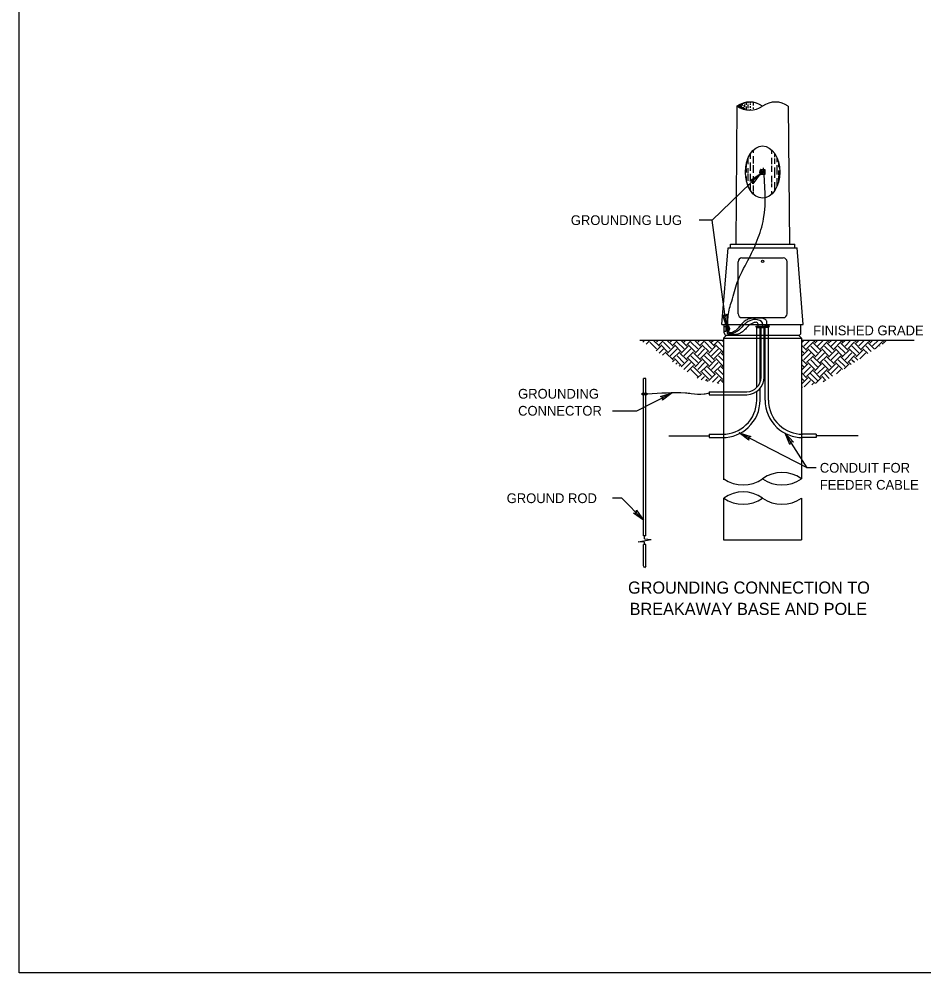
# Model space of a CAD drawing. Extents: x 99978 to 113378, y 99891 to 102182.
# Drawn here: x 99978 to 101096, y 99891 to 101068 of the extents above; entities that cross this region are included whole.
import ezdxf

# ---------------------------------------------------------------- set-up
doc = ezdxf.new("R2010")
doc.units = 0
doc.layers.add('Border Organizer Shape', color=7, linetype='Continuous')
doc.layers.add('Default', color=7, linetype='Continuous')

msp = doc.modelspace()

# ---------------------------------------------------------------- linework, layer by layer
at = {"layer": 'Border Organizer Shape'}
for p, q in [((100865.1, 100960.7), (100863.6, 100790.4)), ((100865.2, 100960.6), (100865.2, 100960.7)), ((100865.5, 100960.4), (100865.5, 100960.9)), ((100865.8, 100960.8), (100865.8, 100961.1)), ((100865.8, 100960.2), (100865.8, 100960.5)), ((100866.2, 100961.1), (100866.2, 100961.4)), ((100866.2, 100960), (100866.2, 100960.9)), ((100866.7, 100961), (100866.7, 100961.7)), ((100866.7, 100959.7), (100866.7, 100960.1)), ((100867.1, 100961), (100867.1, 100961.9)), ((100867.1, 100959.4), (100867.1, 100960.7)), ((100867.7, 100960.5), (100867.7, 100962.3)), ((100867.7, 100959.1), (100867.7, 100959.7)), ((100868.4, 100961.4), (100868.4, 100962.6)), ((100868.4, 100958.7), (100868.4, 100960.4)), ((100869, 100962.3), (100869, 100962.9)), ((100869, 100960.3), (100869, 100961)), ((100869, 100958.4), (100869, 100959.9)), ((100869.7, 100961.9), (100869.7, 100963.2)), ((100869.7, 100961.1), (100869.7, 100961.5)), ((100869.7, 100958.1), (100869.7, 100959.8)), ((100870.7, 100961.7), (100870.7, 100963.7)), ((100870.7, 100958.6), (100870.7, 100960.9)), ((100870.7, 100957.7), (100870.7, 100958.5)), ((100872, 100961.6), (100872, 100964.1)), ((100872, 100957.2), (100872, 100959.6)), ((100873.4, 100963.5), (100873.4, 100964.6)), ((100873.4, 100960.5), (100873.4, 100961.6)), ((100873.4, 100956.8), (100873.4, 100959.6)), ((100875, 100963.8), (100875, 100965)), ((100875, 100959.6), (100875, 100962.9)), ((100875, 100956.3), (100875, 100958.1)), ((100876.9, 100964.3), (100876.9, 100965.3)), ((100876.9, 100962.2), (100876.9, 100964)), ((100876.9, 100957.9), (100876.9, 100960.3)), ((100876.9, 100956), (100876.9, 100957.3)), ((100878.8, 100964.3), (100878.8, 100965.5)), ((100878.8, 100961), (100878.8, 100962.8)), ((100878.8, 100958), (100878.8, 100960.5)), ((100878.8, 100955.8), (100878.8, 100956.7)), ((100881.7, 100964.3), (100881.7, 100965.6)), ((100881.7, 100962.3), (100881.7, 100963.7)), ((100881.7, 100958.7), (100881.7, 100960.5)), ((100881.7, 100955.7), (100881.7, 100956.9)), ((100885.4, 100964.2), (100885.4, 100965.3)), ((100885.4, 100961.5), (100885.4, 100963.8)), ((100885.4, 100957.3), (100885.4, 100959.2)), ((100928.4, 100960.7), (100929.9, 100790.4)), ((100878.8, 100889.1), (100878.8, 100896.7)), ((100881.7, 100895.5), (100881.7, 100902)), ((100885.4, 100903.1), (100885.4, 100906.6)), ((100885.4, 100889.7), (100885.4, 100899.1)), ((100908.1, 100901.8), (100908.1, 100906.6)), ((100908.1, 100889.1), (100908.1, 100897)), ((100911.9, 100897.6), (100911.9, 100902)), ((100876.9, 100885), (100876.9, 100891.1)), ((100881.7, 100880.9), (100881.7, 100891.1)), ((100885.4, 100878.2), (100885.4, 100888)), ((100908.1, 100879.6), (100908.1, 100887.1)), ((100911.9, 100889.5), (100911.9, 100896.1)), ((100911.9, 100872.3), (100911.9, 100884.8)), ((100914.8, 100891.5), (100914.8, 100896.6)), ((100914.8, 100876.2), (100914.8, 100887.8)), ((100916.7, 100885.3), (100916.7, 100890.9)), ((100893.7, 100877), (100834.3, 100819.9)), ((100876.9, 100878.7), (100876.9, 100883.8)), ((100876.9, 100867.5), (100876.9, 100874)), ((100878.8, 100877.7), (100878.8, 100884.2)), ((100878.8, 100868.3), (100878.8, 100876.5)), ((100881.7, 100867.6), (100881.7, 100877.2)), ((100885.4, 100866.5), (100885.4, 100874.3)), ((100896.7, 100880), (100894.1, 100880)), ((100896.7, 100878.6), (100894.1, 100878.6)), ((100908.1, 100866.4), (100908.1, 100874.5)), ((100916.7, 100875), (100916.7, 100881.1)), ((100916.7, 100867.8), (100916.7, 100874.1)), ((100878.8, 100861.9), (100878.8, 100864.4)), ((100881.7, 100856.5), (100881.7, 100864.2)), ((100885.4, 100855.9), (100885.4, 100862.9)), ((100908.1, 100860.8), (100908.1, 100865.1)), ((100911.9, 100856.5), (100911.9, 100867)), ((100914.8, 100862.1), (100914.8, 100871.9)), ((100885.4, 100852), (100885.4, 100854.8)), ((100908.1, 100852.1), (100908.1, 100855.8)), ((100852.3, 100688.7), (100834.3, 100819.9)), ((100846.6, 100691.1), (100854.2, 100785.7)), ((100854.2, 100785.7), (100939.3, 100785.7)), ((100857.1, 100790.4), (100936.4, 100790.4)), ((100857.1, 100785.7), (100857.1, 100790.4)), ((100936.4, 100785.7), (100936.4, 100790.4)), ((100946.9, 100691.1), (100939.3, 100785.7)), ((100866.5, 100704.3), (100866.5, 100768.6)), ((100871.2, 100773.4), (100922.3, 100773.4)), ((100927, 100704.3), (100927, 100768.6)), ((100871.2, 100699.6), (100922.3, 100699.6)), ((100846.6, 100691.1), (100946.9, 100691.1)), ((100849.5, 100680.7), (100849.5, 100691.1)), ((100849.5, 100688.7), (100851.2, 100688.7)), ((100851.2, 100688.7), (100851.2, 100683)), ((100852.2, 100686.8), (100851.2, 100686.8)), ((100852.2, 100684.9), (100851.2, 100684.9)), ((100852.7, 100686.6), (100852.2, 100686.6)), ((100852.7, 100685.1), (100852.2, 100685.1)), ((100855.7, 100686.6), (100855.3, 100686.6)), ((100855.7, 100685.1), (100855.3, 100685.1)), ((100888.3, 100689.1), (100894.3, 100689.1)), ((100889.5, 100687.3), (100888.3, 100689.1)), ((100889.5, 100687.3), (100893.7, 100687.3)), ((100889.5, 100677.8), (100889.5, 100687.3)), ((100893.7, 100689.1), (100899.8, 100689.1)), ((100894.9, 100687.3), (100893.7, 100689.1)), ((100893.7, 100687.3), (100894.3, 100687.9)), ((100893.7, 100677.8), (100893.7, 100687.3)), ((100894.9, 100687.3), (100898.6, 100687.3)), ((100894.9, 100677.8), (100894.9, 100687.3)), ((100898.6, 100687.3), (100899.8, 100689.1)), ((100898.6, 100677.8), (100898.6, 100687.3)), ((100905.2, 100689.1), (100899.2, 100689.1)), ((100899.8, 100687.3), (100899.2, 100687.9)), ((100904, 100687.3), (100899.8, 100687.3)), ((100899.8, 100677.8), (100899.8, 100687.3)), ((100904, 100687.3), (100905.2, 100689.1)), ((100904, 100677.8), (100904, 100687.3)), ((100944.1, 100680.7), (100944.1, 100691.1)), ((100852.3, 100677.8), (100848.6, 100674.2)), ((100848.6, 100674.2), (100944.9, 100674.2)), ((100848.6, 100674.2), (100848.6, 100499.2)), ((100849.5, 100683), (100851.2, 100683)), ((100852.3, 100677.8), (100941.2, 100677.8)), ((100852.3, 100677.8), (100941.2, 100677.8)), ((100889.5, 100613.5), (100889.5, 100677.8)), ((100893.7, 100619.7), (100893.7, 100677.8)), ((100894.9, 100626.4), (100894.9, 100677.8)), ((100898.6, 100626.1), (100898.6, 100677.8)), ((100899.8, 100597.8), (100899.8, 100677.8)), ((100904, 100597.8), (100904, 100677.8)), ((100941.2, 100677.8), (100944.9, 100674.2)), ((100944.9, 100674.2), (100944.9, 100500.7)), ((100745.2, 100671.8), (100848.6, 100671.8)), ((100748.9, 100669.4), (100751.3, 100671.8)), ((100753, 100666.7), (100758.1, 100671.8)), ((100757.4, 100669.4), (100765.9, 100660.9)), ((100761.8, 100671.8), (100769.3, 100664.3)), ((100765.2, 100658.6), (100770.9, 100664.3)), ((100765.8, 100669.4), (100768.2, 100671.8)), ((100769.2, 100666), (100775, 100671.8)), ((100770.9, 100666), (100779.4, 100657.5)), ((100774.3, 100669.4), (100782.8, 100660.9)), ((100778.6, 100671.8), (100786.2, 100664.3)), ((100779.3, 100655.8), (100787.8, 100664.3)), ((100782.8, 100669.4), (100785.2, 100671.8)), ((100786.2, 100666), (100792, 100671.8)), ((100787.9, 100666), (100796.4, 100657.5)), ((100791.3, 100669.4), (100799.8, 100660.9)), ((100795.8, 100671.8), (100803.3, 100664.3)), ((100796.3, 100655.8), (100804.8, 100664.3)), ((100799.7, 100669.4), (100802.1, 100671.8)), ((100803.1, 100666), (100808.9, 100671.8)), ((100804.8, 100666), (100813.3, 100657.5)), ((100808.2, 100669.4), (100816.7, 100660.9)), ((100812.7, 100671.8), (100820.1, 100664.3)), ((100813.3, 100655.9), (100821.8, 100664.4)), ((100816.7, 100669.4), (100819.1, 100671.8)), ((100820.1, 100666), (100825.9, 100671.8)), ((100821.9, 100666.1), (100830.4, 100657.6)), ((100825.3, 100669.5), (100833.8, 100661)), ((100829.8, 100671.8), (100837.2, 100664.4)), ((100830.3, 100655.9), (100838.8, 100664.4)), ((100833.7, 100669.5), (100836, 100671.8)), ((100837.1, 100666.1), (100842.8, 100671.8)), ((100838.8, 100666.1), (100847.3, 100657.6)), ((100842.2, 100669.5), (100848.6, 100663)), ((100846.7, 100671.8), (100848.6, 100669.8)), ((100944.9, 100671.8), (101083.8, 100671.8)), ((100944.9, 100668.5), (100948.2, 100671.8)), ((100944.9, 100665.7), (100951.2, 100659.4)), ((100947.7, 100664.5), (100955, 100671.8)), ((100951.1, 100661.1), (100959.6, 100669.6)), ((100956.2, 100664.5), (100964.7, 100656)), ((100959.2, 100671.8), (100961.4, 100669.6)), ((100959.6, 100667.9), (100968.1, 100659.4)), ((100961.3, 100667.9), (100965.2, 100671.8)), ((100964.7, 100664.5), (100972, 100671.8)), ((100968.1, 100661.1), (100976.6, 100669.6)), ((100969.8, 100661.1), (100978.3, 100652.6)), ((100973.2, 100664.5), (100981.7, 100656)), ((100976, 100671.8), (100978.3, 100669.6)), ((100976.6, 100667.9), (100985.1, 100659.4)), ((100978.2, 100667.9), (100982.1, 100671.8)), ((100981.6, 100664.5), (100988.9, 100671.8)), ((100985, 100661.1), (100993.5, 100669.6)), ((100986.7, 100661.1), (100995.2, 100652.6)), ((100990.1, 100664.5), (100998.6, 100656)), ((100993.2, 100671.8), (100995.4, 100669.6)), ((100993.5, 100667.9), (101002, 100659.4)), ((100995.2, 100667.9), (100999.1, 100671.8)), ((100998.6, 100664.5), (101005.9, 100671.8)), ((101002, 100661.1), (101010.5, 100669.6)), ((101003.8, 100661.2), (101012.3, 100652.7)), ((101007.2, 100664.6), (101015.7, 100656.1)), ((101010.1, 100671.8), (101012.2, 100669.6)), ((101010.6, 100668), (101019.1, 100659.5)), ((101012.2, 100668), (101016, 100671.8)), ((101015.6, 100664.6), (101022.8, 100671.8)), ((101019, 100661.2), (101027.5, 100669.7)), ((101020.7, 100661.2), (101026.7, 100655.1)), ((101024.1, 100664.6), (101030.9, 100657.8)), ((101027.2, 100671.8), (101029.3, 100669.7)), ((101027.5, 100668), (101035, 100660.5)), ((101029.2, 100668), (101033, 100671.8)), ((101032.6, 100664.6), (101039.8, 100671.8)), ((101036, 100661.2), (101044.5, 100669.7)), ((101041.2, 100664.6), (101041.3, 100664.5)), ((101044.1, 100671.8), (101046.2, 100669.7)), ((101044.6, 100668), (101045.5, 100667.2)), ((101046.1, 100668), (101049.9, 100671.8)), ((100769.2, 100655.8), (100774.3, 100660.9)), ((100773.3, 100653.1), (100777.7, 100657.5)), ((100777.7, 100655.8), (100786.2, 100647.3)), ((100782.7, 100652.4), (100791.2, 100660.9)), ((100786.1, 100649), (100794.6, 100657.5)), ((100791.2, 100652.4), (100799.7, 100643.9)), ((100794.6, 100655.8), (100803.1, 100647.3)), ((100799.7, 100652.4), (100808.2, 100660.9)), ((100803.1, 100649), (100811.6, 100657.5)), ((100808.3, 100652.5), (100816.8, 100644)), ((100811.7, 100655.9), (100820.2, 100647.4)), ((100816.7, 100652.5), (100825.2, 100661)), ((100820.1, 100649.1), (100828.6, 100657.6)), ((100825.2, 100652.5), (100833.7, 100644)), ((100828.6, 100655.9), (100837.1, 100647.4)), ((100833.7, 100652.5), (100842.2, 100661)), ((100837.1, 100649.1), (100845.6, 100657.6)), ((100842.3, 100652.5), (100848.6, 100646.2)), ((100845.7, 100655.9), (100848.6, 100653)), ((100847.2, 100655.9), (100848.6, 100657.3)), ((100944.9, 100651.5), (100952.8, 100659.4)), ((100944.9, 100658.9), (100947.8, 100656)), ((100947.7, 100647.4), (100956.2, 100656)), ((100951.1, 100644), (100959.6, 100652.5)), ((100952.8, 100661.1), (100961.3, 100652.5)), ((100959.6, 100650.9), (100968.1, 100642.4)), ((100961.2, 100650.9), (100969.7, 100659.4)), ((100964.6, 100647.5), (100973.1, 100656)), ((100968, 100644.1), (100976.5, 100652.6)), ((100976.5, 100650.9), (100985, 100642.4)), ((100978.2, 100650.9), (100986.7, 100659.4)), ((100981.6, 100647.5), (100990.1, 100656)), ((100985, 100644.1), (100993.5, 100652.6)), ((100993.6, 100651), (101002.1, 100642.5)), ((100995.2, 100651), (101003.7, 100659.5)), ((100998.6, 100647.6), (101007.1, 100656.1)), ((101002, 100644.2), (101010.5, 100652.7)), ((101010.5, 100651), (101014.3, 100647.1)), ((101012.2, 100651), (101020.7, 100659.5)), ((101016.7, 100648.7), (101024.1, 100656.1)), ((100785.5, 100645), (100787.8, 100647.3)), ((100787.8, 100649), (100796.3, 100640.5)), ((100789.6, 100642.3), (100791.2, 100643.9)), ((100793.7, 100639.6), (100794.6, 100640.5)), ((100796.3, 100638.9), (100804.8, 100647.4)), ((100799.7, 100635.5), (100808.2, 100644)), ((100803.8, 100632.8), (100811.6, 100640.6)), ((100804.9, 100649.1), (100813.4, 100640.6)), ((100811.6, 100638.9), (100820.1, 100630.4)), ((100813.3, 100638.9), (100821.8, 100647.4)), ((100816.7, 100635.5), (100825.2, 100644)), ((100820.1, 100632.1), (100828.6, 100640.6)), ((100821.8, 100649.1), (100830.3, 100640.6)), ((100828.6, 100638.9), (100837.2, 100630.4)), ((100830.2, 100638.9), (100838.7, 100647.4)), ((100833.6, 100635.5), (100842.1, 100644)), ((100837, 100632.1), (100845.5, 100640.6)), ((100838.9, 100649.1), (100847.4, 100640.6)), ((100845.5, 100638.9), (100848.6, 100635.8)), ((100847.2, 100638.9), (100848.6, 100640.3)), ((100944.9, 100648.5), (100951.1, 100642.3)), ((100944.9, 100634.6), (100952.7, 100642.4)), ((100944.9, 100641.7), (100947.7, 100638.9)), ((100947.6, 100630.5), (100956.1, 100639)), ((100952.8, 100644.1), (100961.3, 100635.6)), ((100956.2, 100647.5), (100964.7, 100639)), ((100961.2, 100633.9), (100969.7, 100642.4)), ((100964.6, 100630.5), (100973.1, 100639)), ((100969.7, 100644.1), (100978.2, 100635.6)), ((100973.1, 100647.5), (100981.6, 100639)), ((100978.2, 100634), (100986.7, 100642.5)), ((100981.6, 100630.6), (100990.1, 100639.1)), ((100986.8, 100644.2), (100995.3, 100635.7)), ((100990.2, 100647.6), (100998.7, 100639.1)), ((100997.7, 100636.5), (101003.7, 100642.5)), ((101003.7, 100644.2), (101006, 100641.8)), ((101007.1, 100647.6), (101010.2, 100644.5)), ((100808.2, 100635.5), (100816.7, 100627)), ((100816, 100624.7), (100821.7, 100630.4)), ((100821, 100622.9), (100825.1, 100627)), ((100821.8, 100632.1), (100830.3, 100623.6)), ((100825.2, 100635.5), (100833.7, 100627)), ((100830.2, 100621.9), (100838.7, 100630.4)), ((100835, 100619.8), (100842.1, 100627)), ((100838.7, 100632.1), (100847.2, 100623.6)), ((100842.1, 100635.5), (100848.6, 100629)), ((100944.9, 100631.7), (100951.1, 100625.4)), ((100951, 100627.1), (100959.5, 100635.6)), ((100952.7, 100627.1), (100961.2, 100618.6)), ((100956.1, 100630.5), (100964.6, 100622)), ((100959.5, 100633.9), (100968, 100625.4)), ((100968, 100627.1), (100976.5, 100635.6)), ((100969.8, 100627.2), (100975, 100621.9)), ((100973.2, 100630.6), (100979.2, 100624.6)), ((100976.6, 100634), (100983.3, 100627.2)), ((100988.2, 100630.4), (100993.5, 100635.7)), ((100993.5, 100634), (100993.6, 100633.8)), ((100749.8, 100606.2), (100749.8, 100624.4)), ((100752.4, 100624.4), (100749.8, 100624.4)), ((100752.4, 100606.2), (100752.4, 100624.4)), ((100826.6, 100621.7), (100828.5, 100623.6)), ((100828.5, 100621.9), (100829.4, 100621)), ((100840.5, 100618.6), (100845.5, 100623.6)), ((100842.2, 100618.6), (100842.6, 100618.2)), ((100845.6, 100622), (100848.6, 100618.9)), ((100847.2, 100622), (100848.6, 100623.4)), ((100944.9, 100617.5), (100952.7, 100625.4)), ((100944.9, 100624.9), (100947.7, 100622)), ((100944.9, 100614.5), (100946, 100613.4)), ((100948.1, 100614), (100956.1, 100622)), ((100957.7, 100616.8), (100959.5, 100618.6)), ((100962.3, 100618.1), (100969.7, 100625.5)), ((100971.8, 100620.8), (100973.1, 100622)), ((100741.5, 100584.7), (100785.2, 100606.6)), ((100749.8, 100430.3), (100749.8, 100604.4)), ((100752.4, 100430.3), (100752.4, 100604.4)), ((100830.6, 100608.1), (100830.6, 100604.4)), ((100830.6, 100608.1), (100848.6, 100608.1)), ((100830.6, 100604.4), (100848.6, 100604.4)), ((100848.6, 100608.1), (100877.5, 100608.1)), ((100848.6, 100604.4), (100877.5, 100604.4)), ((100889.5, 100597.8), (100889.5, 100607.8)), ((100893.7, 100597.8), (100893.7, 100612)), ((100711.5, 100584.6), (100741.5, 100584.7)), ((100830.6, 100555.7), (100847.4, 100555.7)), ((100830.6, 100555.7), (100830.6, 100551.5)), ((100951.7, 100514.2), (100867.9, 100557.5)), ((100951.7, 100514.2), (100924.7, 100557)), ((100962.9, 100555.7), (100946.1, 100555.7)), ((100962.9, 100555.7), (100962.9, 100551.5)), ((100780.8, 100553.6), (100830.6, 100553.6)), ((100830.6, 100551.5), (100847.4, 100551.5)), ((100962.9, 100551.5), (100946.1, 100551.5)), ((101014.7, 100553.6), (100962.9, 100553.6)), ((100963, 100514.2), (100951.7, 100514.2)), ((100722.9, 100476.6), (100711.6, 100476.6)), ((100749.8, 100449.5), (100722.9, 100476.6)), ((100848.6, 100476.8), (100848.6, 100425.2)), ((100944.9, 100476.8), (100944.9, 100425.2)), ((100742.9, 100422.8), (100759.2, 100425.7)), ((100752.4, 100430.3), (100749.8, 100430.3)), ((100751.1, 100426.4), (100751.1, 100430.3)), ((100751.1, 100426.4), (100759.2, 100425.7)), ((100751.1, 100422.2), (100742.9, 100422.8)), ((100749.8, 100393.2), (100749.8, 100419.5)), ((100752.4, 100419.5), (100749.8, 100419.5)), ((100751.1, 100419.5), (100751.1, 100422.2)), ((100752.4, 100393.2), (100752.4, 100419.5)), ((100848.6, 100425.2), (100944.9, 100425.2)), ((100751.1, 100390.8), (100749.8, 100393.2)), ((100752.4, 100393.2), (100751.1, 100390.8))]:
    msp.add_line(p, q, dxfattribs=at)
for points in [[(100881.2, 100868.5), (100893.7, 100877), (100884.7, 100864.9), (100884.7, 100868.3)], [(100852.8, 100703.8), (100852.3, 100688.7), (100847.8, 100703.1), (100850.6, 100701.1)], [(100754, 100604.4), (100748.1, 100604.4), (100748.1, 100606.2), (100754, 100606.2)], [(100770.7, 100602.2), (100785.2, 100606.6), (100773, 100597.7), (100773.9, 100601)], [(100879.9, 100548.4), (100867.9, 100557.5), (100882.3, 100552.9), (100879, 100551.7)], [(100930.5, 100543), (100924.7, 100557), (100934.8, 100545.7), (100931.4, 100546.4)], [(100741.1, 100461.9), (100749.8, 100449.5), (100737.5, 100458.3), (100740.9, 100458.4)]]:
    msp.add_lwpolyline(points, close=True, dxfattribs=at)
for points in [[(100894.1, 100877.2), (100894.1, 100876.5), (100899.8, 100876.5), (100899.8, 100882.2), (100894.1, 100882.2), (100894.1, 100881.5)], [(100834.3, 100819.9), (100818.5, 100819.9)], [(100853.6, 100688.7), (100852.2, 100688.7), (100852.2, 100683), (100853.6, 100683)], [(100855.7, 100686.6), (100855.7, 100688.7), (100854.3, 100688.7)], [(100854.3, 100683), (100855.7, 100683), (100855.7, 100685.1)]]:
    msp.add_lwpolyline(points, dxfattribs=at)
msp.add_circle((100896.8, 100769), 1.42, dxfattribs=at)
for centre, radius, start, end in [((100880.9, 100938), 27.7, 55.146, 124.854), ((100880.9, 100983.4), 27.7, 235.146, 304.854), ((100912.6, 100938), 27.7, 55.146, 124.854), ((100897.7, 100879.3), 4.54, 141.3402, 218.6598), ((100894.1, 100879.3), 0.709, 90, 270), ((100894.5, 100881.9), 0.454, 38.6598, 141.3402), ((100894.1, 100877.2), 4.26, 40.5831, 89.9989), ((100894.1, 100881.5), 4.26, 269.9969, 319.4163), ((100894.5, 100876.8), 0.454, 218.6598, 321.3402), ((100891.3, 100879.3), 4.54, 8.9819, 25.2023), ((100891.3, 100879.3), 4.54, 334.7901, 351.0122), ((100896.7, 100879.3), 0.709, 270, 90), ((100896.7, 100879.3), 0.895, 314.2773, 45.723), ((100871.2, 100768.6), 4.73, 90, 180), ((100922.3, 100768.6), 4.73, 0, 90), ((100871.2, 100704.3), 4.73, 180, 270), ((100922.3, 100704.3), 4.73, 270, 0), ((100857.2, 100685.9), 4.54, 141.3402, 218.6598), ((100854, 100688.4), 0.454, 38.6598, 141.3402), ((100850.8, 100685.9), 4.54, 321.3402, 38.6598), ((100855.7, 100685.9), 0.709, 270, 90), ((100852.3, 100680.7), 2.84, 180, 270), ((100854, 100683.3), 0.454, 218.6598, 321.3402), ((100941.2, 100680.7), 2.84, 270, 0), ((100876.9, 100626.1), 18, 271.9102, 0), ((100876.9, 100626.1), 21.7, 271.5918, 0), ((100847.4, 100597.8), 42.1, 313.1092, 0.0002), ((100847.4, 100597.8), 46.3, 313.2812, 0.0002), ((100946.1, 100597.8), 46.3, 179.9998, 226.7201), ((100946.1, 100597.8), 42.1, 179.9998, 226.8922), ((100847.4, 100597.8), 42.1, 270, 313.1092), ((100946.1, 100597.8), 42.1, 226.8922, 270), ((100847.4, 100597.8), 46.3, 270, 313.2812), ((100946.1, 100597.8), 46.3, 226.7201, 270), ((100920.7, 100466.9), 41.5, 54.6933, 125.3067), ((100872.8, 100534.6), 41.5, 234.6933, 305.3067), ((100920.7, 100534.6), 41.5, 234.6933, 305.3067), ((100872.8, 100442.9), 41.5, 54.6933, 125.3067), ((100872.8, 100510.6), 41.5, 234.6933, 305.3067), ((100920.7, 100510.6), 41.5, 234.6933, 305.3067)]:
    msp.add_arc(centre, radius, start, end, dxfattribs=at)
msp.add_ellipse((100896.8, 100879.3), major_axis=(0, 32.2), ratio=0.661267, dxfattribs=at)
for points in [[(100854, 100682.4), (100854, 100697.3), (100854.2, 100702), (100858.7, 100720.1), (100865.5, 100743.1), (100878.6, 100770), (100890.2, 100795.1), (100898, 100821.5), (100897.8, 100884.4)], [(100902.2, 100689.1), (100902.1, 100692.8), (100901.9, 100695.2), (100901.2, 100696.4), (100899.3, 100697.8), (100895.4, 100698.9), (100889.3, 100699), (100882.2, 100698.5), (100877.6, 100697), (100873, 100693.8), (100868.9, 100689.1), (100865.3, 100685.2), (100861, 100682), (100858, 100680.9), (100855.3, 100681.2), (100854.2, 100682.7), (100854.3, 100689.7)], [(100896.8, 100689.1), (100896.6, 100693.1), (100887.9, 100697.3), (100878.8, 100694.7), (100871.1, 100688), (100865.7, 100682.8), (100854.7, 100680.7), (100853.8, 100682.9), (100853.8, 100689.7)], [(100891.3, 100689.1), (100891.3, 100691.7), (100890.5, 100693.2), (100888.9, 100693.8), (100886.3, 100693.4), (100882.9, 100692), (100873.1, 100683.2), (100870.7, 100681.3), (100866.3, 100679.3), (100863.3, 100678.6), (100858.1, 100678.4), (100855.5, 100678.4), (100854.2, 100678.6), (100853.4, 100680.2), (100853.5, 100682.9), (100853.6, 100689.7)], [(100830.5, 100606.2), (100824.5, 100604.9), (100808.6, 100605.7), (100801.5, 100606.3), (100754.7, 100605.1)]]:
    msp.add_spline(points, degree=3, dxfattribs=at)
at = {"layer": 'Default'}
msp.add_lwpolyline([(99978.4, 102090.2), (103178.1, 102090.2), (103178.1, 99890.6), (99978.4, 99890.6)], close=True, dxfattribs=at)

# ---------------------------------------------------------------- texts
at = {"layer": 'Border Organizer Shape'}
for s, height, p in [('GROUNDING LUG ', 12, (100659.9, 100813.9)), ('FINISHED GRADE', 12, (100959.3, 100677.8)), ('GROUNDING', 12, (100594.8, 100599.6)), ('CONNECTOR ', 12, (100594.8, 100578.6)), (' CONDUIT FOR ', 12, (100963, 100508.2)), (' FEEDER CABLE', 12, (100963, 100487.2)), ('GROUND ROD ', 12, (100580.7, 100470.6)), ('GROUNDING CONNECTION TO', 15, (100730.6, 100358.8)), ('BREAKAWAY BASE AND POLE', 15, (100732.6, 100332.5))]:
    msp.add_text(s, height=height, dxfattribs=at).set_placement(p)

doc.saveas('drawing.dxf')
